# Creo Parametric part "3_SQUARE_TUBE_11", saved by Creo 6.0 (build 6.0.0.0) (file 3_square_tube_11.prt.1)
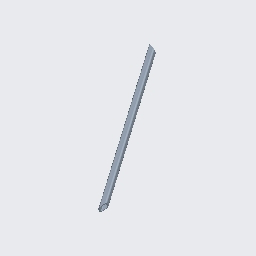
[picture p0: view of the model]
Units: Custom; MM, KILOGRAM, SECS
Materials in the file: STEEL

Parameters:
  BUW_NAME = "SQUARE TUBE"
  BUW_TYPE = "DIN EN 10219"
  BUW_SIZE = "25x25x3.0"
  BUW_LENGTH_STR = "705"
  PTC_MATERIAL_NAME = "STEEL"
  BUW_PROFIL_TYPE = "square_tube"
  BUW_PROFILE_PATH = "parts//profiles/steel_beams_mm/"
  BUW_PROFILE_NAME_LANG = "SQUARE TUBE"
  BUW_TAB_SEL_INFO = "-2 TYPE DIN_EN_10219-1997 SIZE_DINEN_10219 25x25x3.0"
  NAMING = "SQUARE TUBE"
  DESIGNATION = "DIN EN 10219 25x25x3.0 x 705"
  PROFIL_RASTER_POS = "X_0"
  BUW_OBJECT_ROLE = "PROFIL_SYSTEM_BORE_END_POINTS"
  PRO_UNIT_SYS = "Custom"

Other parameters: BUW_LENGTH, LENGTH, BUW_LENGTH_Z_MIN_PARAM, D8, D93, D94, d26, d8, d93, d94, d98, D98, SHEAR_MODULUS, THERM_EXPANSION_REF_TEMPERATURE, STRUCTURAL_DAMPING_COEFFICIENT, STRESS_LIMIT_FOR_TENSION, STRESS_LIMIT_FOR_COMPRESSION, STRESS_LIMIT_FOR_SHEAR, EMISSIVITY

Created from: SQUARE_TUBE.PRT

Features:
  1. datum plane "YZ"
  2. datum plane "XZ"
  3. datum plane "XY"
  4. coordinate system
  5. coordinate system
  6. coordinate system
  7. coordinate system
  8. datum plane "DTM3"
  9. datum plane "DTM4"
  10. datum plane "DTM5"
  11. protrusion
  12. round
  13. round
  14. datum axis
  15. datum point "PNT0"
  16. datum point

Other named items: PROFIL_CUT_QUILT, PROFILE_LENGTH_DIM, CONTACT_SURF_3, CONTACT_SURF_2, CONTACT_SURF_1, CONTACT_SURF_0, E, START_SURFACE, END_SURFACE, SIDE_SURF_3, SIDE_SURF_0, SIDE_SURF_1, SIDE_SURF_2, EDGE_7_S, EDGE_7_E, EDGE_1_S, EDGE_1_E, EDGE_3_S, EDGE_3_E, EDGE_5_S, EDGE_5_E, EDGE_6_S, EDGE_4_S, EDGE_2_S, EDGE_0_S, EDGE_6_E, EDGE_4_E, EDGE_2_E, EDGE_0_E, CS0, CS_S, CS_E, CS3

Named dimensions: X_ROT_S, Y_ROT_S, Z_OFF_S, X_ROT_E, Y_ROT_E, Z_OFF_E, PC_L, BUW_LENGTH_Z_MIN, BUW_LENGTH_DIM

Layers: 00_PROFIL_DATUM, 00_PROFIL_DRW_HIDE, 00_PROFIL_END_CSYS, 00_PROFIL_GEOMETRY, 00_PROFIL_QUILT, 00_PROFIL_SIZE_NOTE

Surfaces: 16 plane, 12 cylinder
